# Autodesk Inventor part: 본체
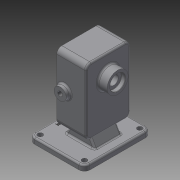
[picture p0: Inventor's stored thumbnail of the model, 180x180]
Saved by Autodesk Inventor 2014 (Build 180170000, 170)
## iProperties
Created: 2020-04
Part Number: 본체
Material: Generic
Document SubType Name: Modeling
Designer: kh
Density: 1 g/cm^3
Appearance: Default
Author: kh
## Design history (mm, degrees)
sketch "스케치1"
  geometry: L1 (-50, -60)-(50, -60); L2 (50, -60)-(50, 60); L3 (50, 60)-(-50, 60); L4 (-50, 60)-(-50, -60); L5 (-50, -60)-(50, 60); L6 (50, -60)-(-50, 60); 1 further point
  constraints: 12 end point, 2 midpoint, 2 parallel, 1 horizontal, 1 perpendicular
  dimensions: "d0" = 100 distance of L3.end L2.end; "d1" = 120 distance of L2.end L1.end
extrude "돌출1" new body sketch "스케치1" distance "d2" = 10; taper "d3" = 0 deg
node "작업 평면1"
sketch "스케치3"
  geometry: L1 (-30, 20)-(-150, 20); L2 (-150, 20)-(-150, 100); L3 (-150, 100)-(-30, 100); L4 (-30, 100)-(-30, 20); L5 (-90, 100)-(-90, 20); L6 (0, 60)-(-22.355, 60); L7 (0, 120)-(0, 0) reference; 1 further point
  constraints: 12 end point, 3 midpoint, 2 parallel, 2 perpendicular, 1 horizontal, 1 point on line
  dimensions: "d10" = 120 distance of L2.end L3.end; "d11" = 80 distance of L1.end L2.end; "d12" = 90 distance from line of L7 L5.start
extrude "돌출3" join sketch "스케치3" distance "d13" = 53; taper "d14" = 0 deg
sketch "스케치4"
  geometry: L1 (-30, 20)-(-150, 20) reference; L2 (-30, 100)-(-30, 20) reference; L3 (-150, 100)-(-30, 100) reference; L4 (-150, 20)-(-150, 100) reference; L5 (0, 60)-(-21.925, 60); L6 (-90, 100)-(-90, 20); C1 r 19 at (-112, 60)
  constraints: 4 end point, 2 midpoint, 1 centre point, 1 perpendicular, 1 point on line
  dimensions: "d15" = 38 diameter of C1; "d16" = 22 distance from line of L6 C1.centre
extrude "돌출4" join sketch "스케치4" stored distance "d17" = 53; taper "d18" = 0 deg
sketch "스케치5"
  geometry: L1 (112, 60)-(68, 60); L2 (112, 84)-(68, 84); L3 (68, 36)-(112, 36); C1 r 19 at (112, 60) reference; A1 r 24 centre (112, 60) between (112, 36) and (112, 84); A2 r 24 centre (68, 60) between (68, 84) and (68, 36); 2 further points
  constraints: 8 end point, 4 point on circle, 4 tangent, 2 centre point, 1 horizontal, 1 midpoint, 1 parallel
  dimensions: "d19" = 44 distance of L1.start L1.end; "d20" = 24 radius of A1
extrude "돌출5" cut sketch "스케치5" distance "d21" = 29; taper "d22" = 0 deg
sketch "스케치6"
  geometry: L1 (68, 84)-(112, 84) reference; L2 (112, 36)-(68, 36) reference; C1 r 12.5 at (112, 60); C2 r 12.5 at (68, 60); A1 r 24 centre (68, 60) between (68, 84) and (68, 36) reference; A2 r 24 centre (112, 60) between (112, 36) and (112, 84) reference; 1 further point
  constraints: 2 centre point, 2 coincident
  dimensions: "d23" = 25 diameter of C1; "d24" = 25 diameter of C2
extrude "돌출6" cut sketch "스케치6" distance "d25" = 15; taper "d26" = 0 deg
sketch "스케치8"
  geometry: C1 r 19 at (0, 0) reference; C2 r 14 at (0, 0); 1 further point
  constraints: 1 centre point, 1 coincident
  dimensions: "d28" = 28 diameter of C2
extrude "돌출7" cut sketch "스케치8" distance "d29" = 7.3; taper "d30" = 0 deg
sketch "스케치9"
  geometry: C1 r 14 at (0, 0) reference; C2 r 8.5 at (0, 0); 1 further point
  constraints: 1 centre point, 1 coincident
  dimensions: "d31" = 17 diameter of C2
extrude "돌출8" cut sketch "스케치9" stored distance "d32" = 7.3; taper "d33" = 0 deg
sketch "스케치12"
  geometry: L1 (33, -40)-(33, 40) reference; L2 (33, 40)-(-20, 40) reference; L3 (-20, -40)-(-20, 40) reference; L4 (33, -40)-(-20, -40) reference; L5 (6, -24)-(7, -24); L6 (7, -24)-(7, 24); L7 (7, 24)-(6, 24); L8 (6, 24)-(6, -24); L9 (0, 0)-(-6.48, 0); L10 (6.5, 40)-(6.5, 35.569); 2 further points
  constraints: 12 end point, 3 midpoint, 3 perpendicular, 2 parallel, 2 point on line, 1 horizontal
  dimensions: "d40" = 1 distance of L7.end L6.end; "d41" = 48 distance of L6.end L5.end
extrude "돌출10" join sketch "스케치12" stored distance "d42" = 7.3; taper "d43" = 0 deg
sketch "스케치13"
  geometry: L1 (50, 0)-(-50, 0) reference; L2 (-50, 0)-(-50, 10) reference; L3 (50, 10)-(-50, 10) reference; L4 (50, 0)-(50, 10) reference; L5 (-33, 30)-(-33, 150) reference; L6 (-33, 150)-(20, 150) reference; L7 (20, 30)-(20, 150) reference; L8 (-33, 30)-(20, 30) reference; L9 (20, 10)-(11.709, 24.361); L10 (-33, 10)-(-25.418, 23.132); 1 further point
  constraints: 4 end point, 2 point on line
  dimensions: "d44" = 60 deg angle of L3 L9; "d46" = 60 deg angle of L3 L10; "d47" = 17 distance from line of L10.start L2; "d48" = 53 distance of L9.start L10.start
  node "투영된 루프8"
  node "투영된 루프9"
feature "리브1" dims "d49" = 1, "d50" = 48, "d51" = 0, "d52" = 0, "d53" = 1, "d54" = 1
feature "리브2" dims "d55" = 1, "d56" = 48, "d57" = 0, "d58" = 0, "d59" = 1, "d60" = 1
node "작업 평면3"
sketch "스케치14"
  geometry: L1 (0, 0)-(0, 120) reference; L2 (0, 120)-(-53, 120) reference; L3 (-53, 0)-(-53, 120) reference; L4 (0, 0)-(-53, 0) reference; L5 (-53, 60)-(-47.567, 60); C1 r 11 at (-39, 60); 1 further point
  constraints: 2 end point, 1 centre point, 1 midpoint, 1 parallel, 1 point on line
  dimensions: "d62" = 22 diameter of C1; "d63" = 14 distance from line of C1.centre L3
extrude "돌출11" join sketch "스케치14" stored distance "d64" = 7.3; taper "d65" = 0 deg
sketch "스케치15"
  geometry: C1 r 11 at (0, 0) reference; 2 further points
  constraints: 1 coincident
hole "구멍1" sketch "스케치15" at (0, 0) diameter "d66" = 8.917; stored, may be unused: countersink angle "d70" = 90 deg, drill point angle "d72" = 118 deg; dims "d67" = 6, "d68" = 4, "d69" = 2, "d71" = 8
fillet "모깎기1" dims "d73" = 9
fillet "모깎기2" dims "d74" = 10
sketch "스케치16"
  geometry: L1 (50, -50)-(50, 50) reference; L2 (-40, -60)-(40, -60) reference; L3 (-50, 50)-(-50, -50) reference; L4 (40, 60)-(-40, 60) reference; A1 r 10 centre (40, 50) between (50, 50) and (40, 60) reference; A2 r 10 centre (40, -50) between (40, -60) and (50, -50) reference; A3 r 10 centre (-40, -50) between (-50, -50) and (-40, -60) reference; A4 r 10 centre (-40, 50) between (-40, 60) and (-50, 50) reference; 5 further points
  constraints: 4 coincident
hole "구멍2" sketch "스케치16" at (-40, 50), (40, 50), (40, -50), (-40, -50) diameter "d75" = 9; stored, may be unused: countersink angle "d79" = 90 deg, drill point angle "d81" = 118 deg; dims "d76" = 6, "d77" = 4, "d78" = 2, "d80" = 8
fillet "모깎기3" dims "d82" = 3
fillet "모깎기4" dims "d83" = 3
fillet "모깎기5" dims "d84" = 3
fillet "모깎기6" dims "d85" = 3
chamfer "모따기1" distance "d86" = 0.7; stored, may be unused: second distance "d87" = 2, angle "d88" = 30 deg
fillet "모깎기7" dims "d89" = 0.5
chamfer "모따기2" distance "d90" = 1; stored, may be unused: second distance "d91" = 2, angle "d92" = 30 deg
sketch "스케치17"
  geometry: L1 (-36.998, 20.739)-(-36.998, -20.739); L2 (-36.998, -20.739)-(-43.002, -20.739); L3 (-43.002, -20.739)-(-43.002, 20.739); L4 (-43.002, 20.739)-(-36.998, 20.739); L5 (-43.002, 20.739)-(-36.998, -20.739); L6 (-50, 50)-(-50, -50) reference; L7 (40, 60)-(-40, 60) reference; 2 further points
  constraints: 2 end point, 1 midpoint, 2 other
  dimensions: "d93" = 10 distance from line of point (-40, 0) L6; "d94" = 60 distance from line of point (-40, 0) L7
feature "엠보싱1" sketch "스케치17" dims "d95" = 0.5, "d96" = 0
sketch "스케치18"
  geometry: L1 (68, 84)-(112, 84) reference; L2 (112, 36)-(68, 36) reference; L3 (30, 91)-(30, 29) reference; L4 (39, 20)-(90, 20) reference; L5 (90, 20)-(141, 20) reference; L6 (150, 29)-(150, 91) reference; L7 (141, 100)-(90, 100) reference; L8 (90, 100)-(39, 100) reference; A1 r 24 centre (68, 60) between (68, 84) and (68, 36) reference; A2 r 24 centre (112, 60) between (112, 36) and (112, 84) reference; A3 r 9 centre (39, 91) between (39, 100) and (30, 91) reference; A4 r 9 centre (39, 29) between (30, 29) and (39, 20) reference; A5 r 9 centre (141, 29) between (141, 20) and (150, 29) reference; A6 r 9 centre (141, 91) between (150, 91) and (141, 100) reference; 2 further points
  constraints: 1 coincident
hole "구멍3" sketch "스케치18" at (141, 91) diameter "d97" = 4.459; stored, may be unused: countersink angle "d101" = 90 deg, drill point angle "d103" = 118 deg; dims "d98" = 10, "d99" = 4, "d100" = 2, "d102" = 12
node "작업 평면4"
node "솔리드1"
mirror "대칭1"
pattern_linear "직사각형 패턴1" dims "d106" = 62, "d109" = 29
mirror "대칭2"
node "투영된 루프1"
node "투영된 루프2"
node "투영된 루프4"
node "투영된 루프5"
node "투영된 루프7"
node "투영된 루프10"
node "투영된 루프11"
node "투영된 루프12"
node "투영된 루프13"
other parameters: "d9" = -17, "d61" = 8
